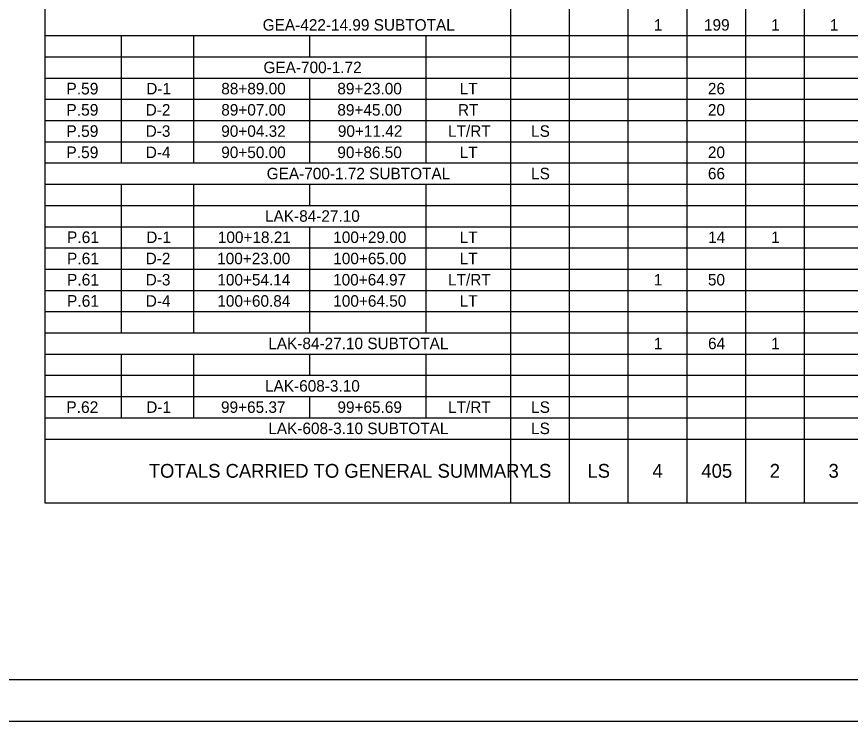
# Model space of a CAD drawing. Extents: x 0 to 34, y 0 to 22.
# Drawn here: x 14.08 to 24.1, y 0 to 8.46 of the extents above; entities that cross this region are included whole.
import ezdxf

# ---------------------------------------------------------------- set-up
doc = ezdxf.new("R2010")
doc.units = 0
for name, color, linetype in [('SH_Border', 7, 'Continuous'), ('SH_Cut_Line', 7, 'Continuous'), ('SH_Text', 7, 'Continuous')]:
    doc.layers.add(name, color=color, linetype=linetype)

msp = doc.modelspace()

# ---------------------------------------------------------------- linework, layer by layer
at = {"layer": 'SH_Border'}
msp.add_lwpolyline([(1.5, 21.5), (33.5, 21.5), (33.5, 0.5), (1.5, 0.5)], close=True, dxfattribs=at)
at = {"layer": 'SH_Cut_Line'}
msp.add_lwpolyline([(0, 0), (34, 0), (34, 22), (0, 22)], close=True, dxfattribs=at)
at = {"layer": 'SH_Text'}
for p, q in [((14.42, 21), (14.42, 2.625)), ((20.015, 21), (20.015, 2.625)), ((20.72, 20.745), (20.72, 2.625)), ((21.425, 20.745), (21.425, 2.625)), ((22.13, 20.745), (22.13, 2.625)), ((22.835, 20.745), (22.835, 2.625)), ((23.54, 20.745), (23.54, 2.625)), ((14.42, 8.235), (31.295, 8.235)), ((15.335, 8.235), (15.335, 6.705)), ((16.205, 8.235), (16.205, 6.705)), ((17.6, 8.235), (17.6, 7.98)), ((18.995, 8.235), (18.995, 6.705)), ((14.42, 7.98), (31.295, 7.98)), ((14.42, 7.725), (31.295, 7.725)), ((17.6, 7.725), (17.6, 6.705)), ((14.42, 7.47), (31.295, 7.47)), ((14.42, 7.215), (31.295, 7.215)), ((14.42, 6.96), (31.295, 6.96)), ((14.42, 6.705), (31.295, 6.705)), ((14.42, 6.45), (31.295, 6.45)), ((15.335, 6.45), (15.335, 4.665)), ((16.205, 6.45), (16.205, 4.665)), ((17.6, 6.45), (17.6, 6.195)), ((18.995, 6.45), (18.995, 4.665)), ((14.42, 6.195), (31.295, 6.195)), ((14.42, 5.94), (31.295, 5.94)), ((17.6, 5.94), (17.6, 4.665)), ((14.42, 5.685), (31.295, 5.685)), ((14.42, 5.43), (31.295, 5.43)), ((14.42, 5.175), (31.295, 5.175)), ((14.42, 4.92), (31.295, 4.92)), ((14.42, 4.665), (31.295, 4.665)), ((14.42, 4.41), (31.295, 4.41)), ((15.335, 4.41), (15.335, 3.645)), ((16.205, 4.41), (16.205, 3.645)), ((17.6, 4.41), (17.6, 4.155)), ((18.995, 4.41), (18.995, 3.645)), ((14.42, 4.155), (31.295, 4.155)), ((14.42, 3.9), (31.295, 3.9)), ((17.6, 3.9), (17.6, 3.645)), ((14.42, 3.645), (31.295, 3.645)), ((14.42, 3.39), (31.295, 3.39)), ((14.42, 2.625), (31.295, 2.625))]:
    msp.add_line(p, q, dxfattribs=at)

# ---------------------------------------------------------------- texts
for s, height, p in [('GEA-422-14.99 SUBTOTAL', 0.138, (17.036, 8.294)), ('1', 0.138, (21.736, 8.294)), ('199', 0.138, (22.338, 8.294)), ('1', 0.138, (23.146, 8.294)), ('1', 0.138, (23.851, 8.294)), ('GEA-700-1.72', 0.138, (17.045, 7.784)), ('P.59', 0.14, (14.677, 7.528)), ('D-1', 0.138, (15.637, 7.529)), ('88+89.00', 0.138, (16.538, 7.529)), ('89+23.00', 0.138, (17.933, 7.529)), ('LT', 0.138, (19.402, 7.529)), ('26', 0.138, (22.385, 7.529)), ('P.59', 0.14, (14.677, 7.273)), ('D-2', 0.138, (15.63, 7.274)), ('89+07.00', 0.138, (16.538, 7.274)), ('89+45.00', 0.138, (17.933, 7.274)), ('20', 0.138, (22.385, 7.274)), ('RT', 0.138, (19.382, 7.274)), ('P.59', 0.14, (14.677, 7.018)), ('D-3', 0.138, (15.63, 7.019)), ('90+04.32', 0.138, (16.538, 7.019)), ('90+11.42', 0.138, (17.939, 7.019)), ('LT/RT', 0.138, (19.263, 7.019)), ('LS', 0.138, (20.261, 7.019)), ('P.59', 0.14, (14.677, 6.763)), ('D-4', 0.138, (15.631, 6.764)), ('90+50.00', 0.138, (16.538, 6.764)), ('90+86.50', 0.138, (17.933, 6.764)), ('LT', 0.138, (19.402, 6.764)), ('20', 0.138, (22.385, 6.764)), ('GEA-700-1.72 SUBTOTAL', 0.138, (17.084, 6.509)), ('LS', 0.138, (20.261, 6.509)), ('66', 0.138, (22.385, 6.509)), ('LAK-84-27.10', 0.138, (17.064, 5.999)), ('P.61', 0.14, (14.684, 5.743)), ('D-1', 0.138, (15.637, 5.744)), ('100+18.21', 0.138, (16.497, 5.744)), ('100+29.00', 0.138, (17.884, 5.744)), ('LT', 0.138, (19.402, 5.744)), ('14', 0.138, (22.387, 5.744)), ('1', 0.138, (23.146, 5.744)), ('P.61', 0.14, (14.684, 5.488)), ('D-2', 0.138, (15.63, 5.489)), ('100+23.00', 0.138, (16.489, 5.489)), ('100+65.00', 0.138, (17.884, 5.489)), ('LT', 0.138, (19.402, 5.489)), ('P.61', 0.14, (14.684, 5.233)), ('D-3', 0.138, (15.63, 5.234)), ('100+54.14', 0.138, (16.491, 5.234)), ('100+64.97', 0.138, (17.882, 5.234)), ('LT/RT', 0.138, (19.263, 5.234)), ('1', 0.138, (21.736, 5.234)), ('50', 0.138, (22.385, 5.234)), ('P.61', 0.14, (14.684, 4.978)), ('D-4', 0.138, (15.631, 4.979)), ('100+60.84', 0.138, (16.491, 4.979)), ('100+64.50', 0.138, (17.884, 4.979)), ('LT', 0.138, (19.402, 4.979)), ('LAK-84-27.10 SUBTOTAL', 0.138, (17.103, 4.469)), ('64', 0.138, (22.387, 4.469)), ('1', 0.138, (21.736, 4.469)), ('1', 0.138, (23.146, 4.469)), ('LAK-608-3.10', 0.138, (17.064, 3.959)), ('P.62', 0.14, (14.676, 3.703)), ('D-1', 0.138, (15.637, 3.704)), ('99+65.37', 0.138, (16.535, 3.704)), ('99+65.69', 0.138, (17.934, 3.704)), ('LT/RT', 0.138, (19.263, 3.704)), ('LS', 0.138, (20.261, 3.704)), ('LAK-608-3.10 SUBTOTAL', 0.138, (17.103, 3.449)), ('LS', 0.138, (20.261, 3.449)), ('TOTALS CARRIED TO GENERAL SUMMARY', 0.1656, (15.667, 2.925)), ('LS', 0.1656, (20.233, 2.925)), ('LS', 0.1656, (20.938, 2.925)), ('4', 0.166, (21.719, 2.925)), ('405', 0.1656, (22.307, 2.925)), ('2', 0.166, (23.128, 2.925)), ('3', 0.166, (23.834, 2.925))]:
    msp.add_text(s, height=height, dxfattribs=at).set_placement(p)

doc.saveas('drawing.dxf')
